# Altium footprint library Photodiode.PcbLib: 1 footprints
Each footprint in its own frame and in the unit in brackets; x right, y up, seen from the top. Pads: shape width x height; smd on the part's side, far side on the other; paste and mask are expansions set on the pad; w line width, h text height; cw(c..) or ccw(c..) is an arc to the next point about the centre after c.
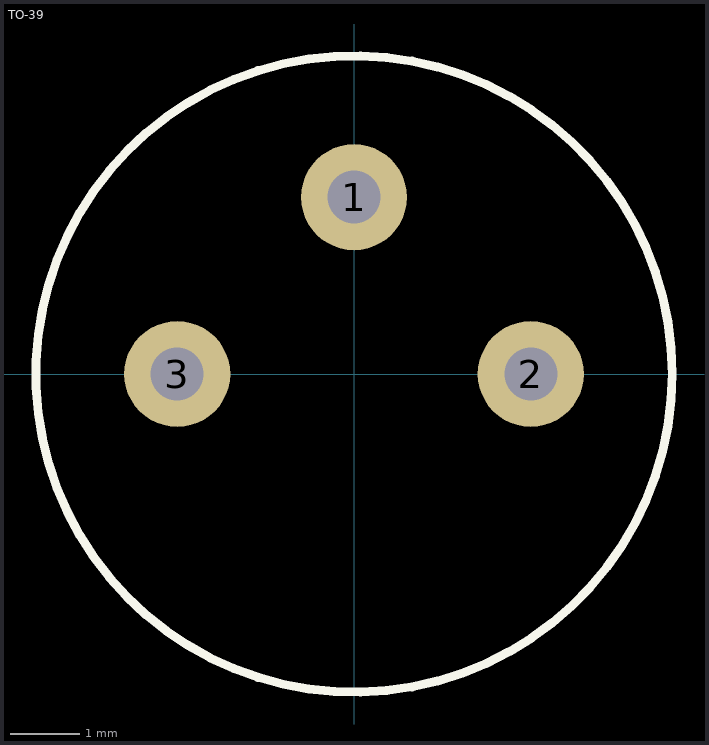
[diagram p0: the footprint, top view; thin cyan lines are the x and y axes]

## TO-39 [mil]
pads (3):
  round 60 hole 30: 1(0,100) 2(100,0) 3(-100,0)
Top Overlay:
  circle w5: c0,0 r180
